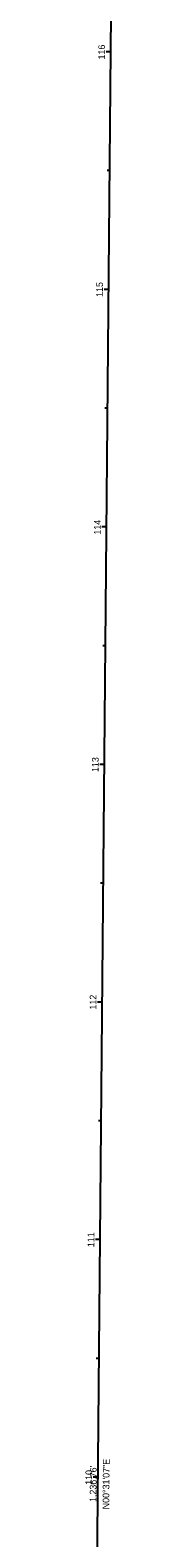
# Model space of a CAD drawing. Extents: x 177110 to 177558, y 286252 to 294117.
# Drawn here: x 177157 to 177168, y 286847 to 287482 of the extents above; entities that cross this region are included whole.
import ezdxf

# ---------------------------------------------------------------- set-up
doc = ezdxf.new("R2010")
doc.units = 0
for name, color, linetype in [('GE_X_Alignment_500_Bearings', 7, 'Continuous'), ('GE_X_Alignment_500_Distances', 7, 'Continuous'), ('GE_X_Alignment_500_Stations', 7, 'Continuous'), ('RW_X_CL', 7, 'Continuous'), ('RW_X_CL_100_Bearings', 7, 'Continuous'), ('RW_X_CL_100_Distances', 7, 'Continuous'), ('RW_X_CL_100_Stations', 7, 'Continuous')]:
    doc.layers.add(name, color=color, linetype=linetype)

msp = doc.modelspace()

# ---------------------------------------------------------------- linework, layer by layer
at = {"layer": 'GE_X_Alignment_500_Stations'}
for p, q in [((177168.16, 287473.01), (177166.96, 287473.02)), ((177167.26, 287373.01), (177165.26, 287373.03)), ((177166.35, 287273.02), (177165.15, 287273.03)), ((177165.45, 287173.02), (177164.25, 287173.03)), ((177164.54, 287073.03), (177163.34, 287073.04)), ((177163.64, 286973.03), (177162.44, 286973.04)), ((177162.73, 286873.03), (177160.73, 286873.05))]:
    msp.add_line(p, q, dxfattribs=at)
at = {"layer": 'RW_X_CL'}
msp.add_line((177157.11, 286252.3), (177168.31, 287489.01), dxfattribs=at)
at = {"layer": 'RW_X_CL_100_Stations'}
for p, q in [((177168.16, 287473.01), (177166.16, 287473.03)), ((177167.71, 287423.01), (177166.51, 287423.02)), ((177167.26, 287373.01), (177165.26, 287373.03)), ((177166.8, 287323.02), (177165.6, 287323.03)), ((177166.35, 287273.02), (177164.35, 287273.04)), ((177165.9, 287223.02), (177164.7, 287223.03)), ((177165.45, 287173.02), (177163.45, 287173.04)), ((177164.99, 287123.02), (177163.79, 287123.03)), ((177164.54, 287073.03), (177162.54, 287073.04)), ((177164.09, 287023.03), (177162.89, 287023.04)), ((177163.64, 286973.03), (177161.64, 286973.05)), ((177163.18, 286923.03), (177161.98, 286923.04)), ((177162.73, 286873.03), (177160.73, 286873.05))]:
    msp.add_line(p, q, dxfattribs=at)

# ---------------------------------------------------------------- texts
at = {"layer": 'GE_X_Alignment_500_Bearings'}
msp.add_text('N00°31\'07"E', height=2.8, rotation=89.48145, dxfattribs=at).set_placement((177167.41, 286859.49))
at = {"layer": 'GE_X_Alignment_500_Distances'}
msp.add_text("1,236.76'", height=2.8, rotation=89.48145, dxfattribs=at).set_placement((177162.01, 286862.56))
at = {"layer": 'GE_X_Alignment_500_Stations'}
for s, p in [('115', (177164.73, 287369.83)), ('110', (177160.2, 286869.79))]:
    msp.add_text(s, height=2.8, rotation=89.48145, dxfattribs=at).set_placement(p)
at = {"layer": 'RW_X_CL_100_Bearings'}
msp.add_text('N00°31\'07"E', height=2.8, rotation=89.48145, dxfattribs=at).set_placement((177167.41, 286859.49))
at = {"layer": 'RW_X_CL_100_Distances'}
msp.add_text("1,236.76'", height=2.8, rotation=89.48145, dxfattribs=at).set_placement((177162.01, 286862.56))
at = {"layer": 'RW_X_CL_100_Stations'}
for s, p in [('116', (177165.63, 287469.78)), ('115', (177164.73, 287369.83)), ('114', (177163.82, 287269.76)), ('113', (177162.92, 287169.85)), ('112', (177162.01, 287069.84)), ('111', (177161.11, 286969.83)), ('110', (177160.2, 286869.79))]:
    msp.add_text(s, height=2.8, rotation=89.48145, dxfattribs=at).set_placement(p)

doc.saveas('drawing.dxf')
